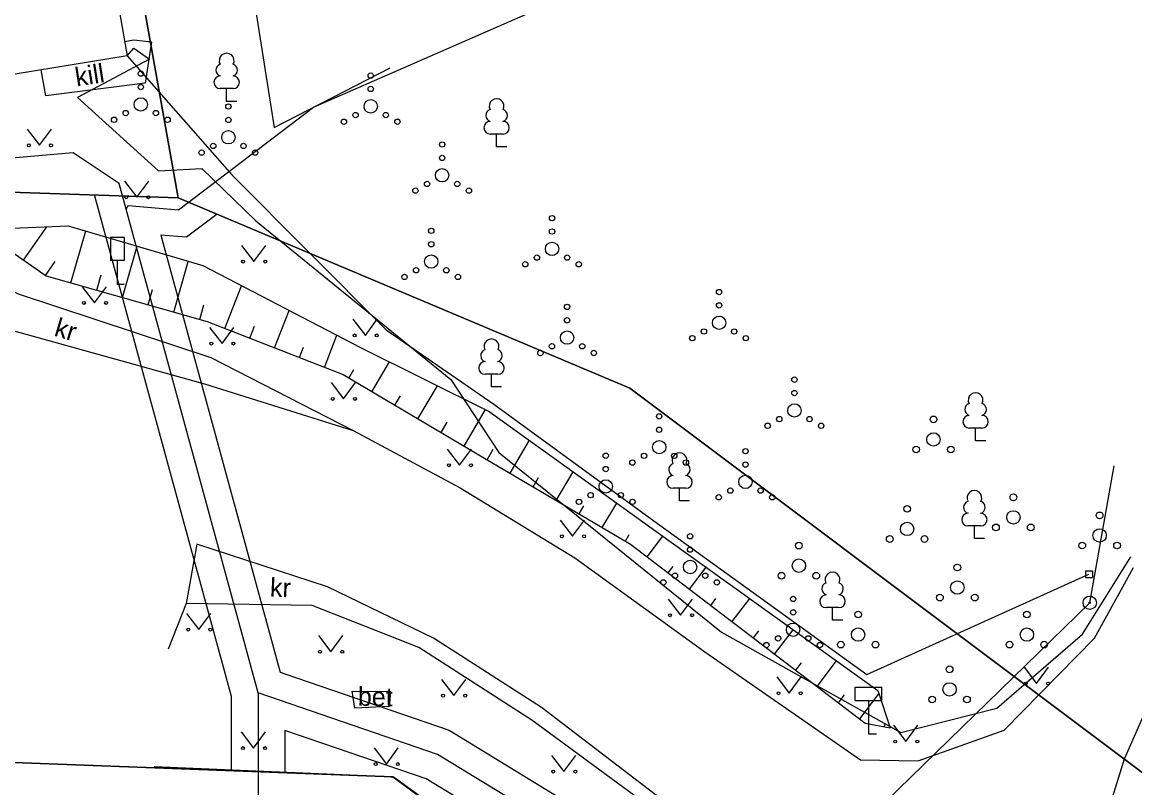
# Model space of a CAD drawing. Extents: x 554947 to 555436, y 6564938 to 6565792.
# Drawn here: x 555228.52 to 555270.11, y 6565583.53 to 6565612.16 of the extents above; entities that cross this region are included whole.
import ezdxf

# ---------------------------------------------------------------- set-up
doc = ezdxf.new("R2010")
doc.units = 0
for name, color, linetype in [('AED', 7, 'Continuous'), ('HALJASTUS', 7, 'Continuous'), ('HOONE', 7, 'Continuous'), ('KASUTUSALA', 7, 'Continuous'), ('LIIKLUS', 7, 'Continuous'), ('MPKAABEL', 7, 'Continuous'), ('MPOHULIIN', 7, 'Continuous'), ('PIIR', 7, 'Continuous'), ('POST', 7, 'Continuous'), ('PR_SIDE', 7, 'Continuous'), ('PUU', 7, 'Continuous'), ('RELJEEF', 7, 'Continuous'), ('TEE', 7, 'Continuous')]:
    doc.layers.add(name, color=color, linetype=linetype)

msp = doc.modelspace()

# ---------------------------------------------------------------- linework, layer by layer
at = {"layer": 'AED'}
for p, q in [((555268.277, 6565591.648), (555268.277, 6565591.398)), ((555268.277, 6565591.648), (555268.527, 6565591.648)), ((555268.527, 6565591.648), (555268.527, 6565591.398)), ((555268.277, 6565591.398), (555268.527, 6565591.398))]:
    msp.add_line(p, q, dxfattribs=at)
for points in [[(555232.436, 6565610.906), (555236.358, 6565606.45), (555242.129, 6565600.656), (555246.155, 6565597.882), (555252.128, 6565593.519), (555260.095, 6565587.775), (555268.402, 6565591.523)], [(555257.388, 6565572.989), (555251.782, 6565577.142), (555242.434, 6565583.901), (555242.233, 6565583.941), (555233.453, 6565584.321)]]:
    msp.add_lwpolyline(points, dxfattribs=at)
at = {"layer": 'HALJASTUS'}
for p, q in [((555228.702, 6565608.164), (555229.166, 6565607.558)), ((555229.166, 6565607.558), (555229.611, 6565608.164)), ((555232.345, 6565606.223), (555232.808, 6565605.616)), ((555232.808, 6565605.616), (555233.254, 6565606.223)), ((555236.713, 6565603.817), (555237.176, 6565603.21)), ((555237.176, 6565603.21), (555237.622, 6565603.817)), ((555230.761, 6565602.272), (555231.225, 6565601.665)), ((555231.225, 6565601.665), (555231.67, 6565602.272)), ((555240.883, 6565601.058), (555241.346, 6565600.451)), ((555241.346, 6565600.451), (555241.792, 6565601.058)), ((555235.524, 6565600.751), (555235.988, 6565600.144)), ((555235.988, 6565600.144), (555236.433, 6565600.751)), ((555240.066, 6565598.683), (555240.53, 6565598.076)), ((555240.53, 6565598.076), (555240.975, 6565598.683)), ((555244.406, 6565596.2), (555244.87, 6565595.593)), ((555244.87, 6565595.593), (555245.315, 6565596.2)), ((555248.633, 6565593.543), (555249.097, 6565592.937)), ((555249.097, 6565592.937), (555249.542, 6565593.543)), ((555252.67, 6565590.593), (555253.134, 6565589.986)), ((555253.134, 6565589.986), (555253.579, 6565590.593)), ((555234.659, 6565590.056), (555235.122, 6565589.45)), ((555235.122, 6565589.45), (555235.568, 6565590.056)), ((555239.59, 6565589.226), (555240.053, 6565588.62)), ((555240.053, 6565588.62), (555240.499, 6565589.226)), ((555265.979, 6565588.04), (555266.442, 6565587.434)), ((555266.442, 6565587.434), (555266.888, 6565588.04)), ((555244.191, 6565587.586), (555244.655, 6565586.979)), ((555244.655, 6565586.979), (555245.1, 6565587.586)), ((555256.732, 6565587.677), (555257.195, 6565587.07)), ((555257.195, 6565587.07), (555257.641, 6565587.677)), ((555236.705, 6565585.623), (555237.169, 6565585.017)), ((555237.169, 6565585.017), (555237.614, 6565585.623)), ((555261.092, 6565585.871), (555261.555, 6565585.264)), ((555261.555, 6565585.264), (555262.001, 6565585.871)), ((555241.67, 6565585.027), (555242.133, 6565584.421)), ((555242.133, 6565584.421), (555242.579, 6565585.027)), ((555248.307, 6565584.746), (555248.77, 6565584.139)), ((555248.77, 6565584.139), (555249.216, 6565584.746))]:
    msp.add_line(p, q, dxfattribs=at)
for points in [[(555237.448, 6565630.434), (555234.711, 6565628.766), (555234.594, 6565621.78), (555237.038, 6565613.917), (555237.935, 6565608.224), (555242.277, 6565610.46)], [(555232.436, 6565610.906), (555232.688, 6565611.189), (555233.276, 6565610.777), (555230.59, 6565609.352), (555233.609, 6565606.609), (555235.228, 6565606.695), (555237.256, 6565604.74), (555244.547, 6565598.797), (555246.343, 6565596.071), (555254.665, 6565589.351), (555261.368, 6565585.597), (555264.956, 6565586.512), (555268.159, 6565589.281), (555269.967, 6565592.17)]]:
    msp.add_lwpolyline(points, dxfattribs=at)
for centre, radius in [((555232.951, 6565610.238), 0.1), ((555241.546, 6565610.166), 0.1), ((555232.951, 6565609.738), 0.1), ((555241.546, 6565609.666), 0.1), ((555232.951, 6565609.088), 0.25), ((555236.225, 6565609.009), 0.1), ((555241.546, 6565609.016), 0.25), ((555231.951, 6565608.513), 0.1), ((555232.386, 6565608.763), 0.1), ((555233.516, 6565608.763), 0.1), ((555233.951, 6565608.513), 0.1), ((555236.225, 6565608.509), 0.1), ((555240.546, 6565608.441), 0.1), ((555240.981, 6565608.691), 0.1), ((555242.111, 6565608.691), 0.1), ((555242.546, 6565608.441), 0.1), ((555236.225, 6565607.859), 0.25), ((555244.218, 6565607.588), 0.1), ((555228.765, 6565607.558), 0.055), ((555229.593, 6565607.558), 0.055), ((555235.225, 6565607.284), 0.1), ((555235.66, 6565607.534), 0.1), ((555236.79, 6565607.534), 0.1), ((555237.225, 6565607.284), 0.1), ((555244.218, 6565607.088), 0.1), ((555244.218, 6565606.438), 0.25), ((555243.653, 6565606.113), 0.1), ((555244.783, 6565606.113), 0.1), ((555232.407, 6565605.616), 0.055), ((555233.236, 6565605.616), 0.055), ((555243.218, 6565605.863), 0.1), ((555245.218, 6565605.863), 0.1), ((555248.326, 6565604.835), 0.1), ((555243.809, 6565604.36), 0.1), ((555248.326, 6565604.335), 0.1), ((555243.809, 6565603.86), 0.1), ((555248.326, 6565603.685), 0.25), ((555236.775, 6565603.21), 0.055), ((555237.604, 6565603.21), 0.055), ((555243.809, 6565603.21), 0.25), ((555247.326, 6565603.11), 0.1), ((555247.761, 6565603.36), 0.1), ((555248.891, 6565603.36), 0.1), ((555249.326, 6565603.11), 0.1), ((555242.809, 6565602.635), 0.1), ((555243.244, 6565602.885), 0.1), ((555244.374, 6565602.885), 0.1), ((555244.809, 6565602.635), 0.1), ((555254.571, 6565602.071), 0.1), ((555230.824, 6565601.665), 0.055), ((555231.652, 6565601.665), 0.055), ((555248.889, 6565601.517), 0.1), ((555254.571, 6565601.571), 0.1), ((555248.889, 6565601.017), 0.1), ((555254.571, 6565600.921), 0.25), ((555248.889, 6565600.367), 0.25), ((555254.006, 6565600.596), 0.1), ((555255.136, 6565600.596), 0.1), ((555235.587, 6565600.144), 0.055), ((555236.415, 6565600.144), 0.055), ((555240.945, 6565600.451), 0.055), ((555241.774, 6565600.451), 0.055), ((555253.571, 6565600.346), 0.1), ((555255.571, 6565600.346), 0.1), ((555247.889, 6565599.792), 0.1), ((555248.324, 6565600.042), 0.1), ((555249.454, 6565600.042), 0.1), ((555249.889, 6565599.792), 0.1), ((555257.388, 6565598.795), 0.1), ((555240.129, 6565598.076), 0.055), ((555240.957, 6565598.076), 0.055), ((555257.388, 6565598.295), 0.1), ((555257.388, 6565597.645), 0.25), ((555252.332, 6565597.421), 0.1), ((555256.823, 6565597.32), 0.1), ((555257.953, 6565597.32), 0.1), ((555252.332, 6565596.921), 0.1), ((555256.388, 6565597.07), 0.1), ((555258.388, 6565597.07), 0.1), ((555252.332, 6565596.271), 0.25), ((555250.334, 6565595.952), 0.1), ((555251.767, 6565595.946), 0.1), ((555252.897, 6565595.946), 0.1), ((555255.558, 6565596.121), 0.1), ((555244.469, 6565595.593), 0.055), ((555245.297, 6565595.593), 0.055), ((555251.332, 6565595.696), 0.1), ((555253.332, 6565595.696), 0.1), ((555255.558, 6565595.621), 0.1), ((555250.334, 6565595.452), 0.1), ((555255.558, 6565594.971), 0.25), ((555250.334, 6565594.802), 0.25), ((555249.769, 6565594.477), 0.1), ((555250.899, 6565594.477), 0.1), ((555254.558, 6565594.396), 0.1), ((555254.993, 6565594.646), 0.1), ((555256.123, 6565594.646), 0.1), ((555256.558, 6565594.396), 0.1), ((555249.334, 6565594.227), 0.1), ((555251.334, 6565594.227), 0.1), ((555248.696, 6565592.937), 0.055), ((555249.525, 6565592.937), 0.055), ((555253.488, 6565592.94), 0.1), ((555253.488, 6565592.44), 0.1), ((555253.488, 6565591.79), 0.25), ((555252.923, 6565591.465), 0.1), ((555254.053, 6565591.465), 0.1), ((555252.488, 6565591.215), 0.1), ((555254.488, 6565591.215), 0.1), ((555257.341, 6565590.594), 0.1), ((555257.341, 6565590.094), 0.1), ((555252.733, 6565589.986), 0.055), ((555253.561, 6565589.986), 0.055), ((555234.721, 6565589.45), 0.055), ((555235.55, 6565589.45), 0.055), ((555257.341, 6565589.444), 0.25), ((555256.341, 6565588.869), 0.1), ((555256.776, 6565589.119), 0.1), ((555257.906, 6565589.119), 0.1), ((555258.341, 6565588.869), 0.1), ((555239.652, 6565588.62), 0.055), ((555240.481, 6565588.62), 0.055), ((555266.041, 6565587.434), 0.055), ((555266.87, 6565587.434), 0.055), ((555244.254, 6565586.979), 0.055), ((555245.082, 6565586.979), 0.055), ((555256.794, 6565587.07), 0.055), ((555257.623, 6565587.07), 0.055), ((555261.154, 6565585.264), 0.055), ((555261.983, 6565585.264), 0.055), ((555236.768, 6565585.017), 0.055), ((555237.597, 6565585.017), 0.055), ((555241.732, 6565584.421), 0.055), ((555242.561, 6565584.421), 0.055), ((555248.369, 6565584.139), 0.055), ((555249.198, 6565584.139), 0.055)]:
    msp.add_circle(centre, radius, dxfattribs=at)
at = {"layer": 'HOONE'}
msp.add_lwpolyline([(555227.207, 6565620.08), (555230.727, 6565620.695), (555232.436, 6565610.906), (555223.594, 6565609.458), (555222.944, 6565613.428)], dxfattribs=at)
at = {"layer": 'KASUTUSALA'}
msp.add_lwpolyline([(555282.937, 6565554.541), (555264.078, 6565568.633), (555259.865, 6565571.933), (555249.017, 6565580.573), (555243.622, 6565583.862), (555238.34, 6565585.678), (555238.34, 6565584.092), (555236.34, 6565584.168), (555236.34, 6565586.946), (555231.217, 6565605.702), (555233.309, 6565605.634), (555234.35, 6565605.6), (555235.803, 6565604.987), (555234.66, 6565604.12), (555233.701, 6565604.199), (555238.103, 6565588.08), (555238.166, 6565587.854), (555238.34, 6565587.793), (555244.478, 6565585.683), (555250.166, 6565582.216), (555261.104, 6565573.503), (555265.293, 6565570.221), (555284.174, 6565556.114)], dxfattribs=at)
at = {"layer": 'LIIKLUS'}
for p, q in [((555231.823, 6565604.106), (555231.823, 6565603.256)), ((555232.323, 6565604.106), (555231.823, 6565604.106)), ((555232.323, 6565604.106), (555232.323, 6565603.256)), ((555232.323, 6565603.256), (555231.823, 6565603.256)), ((555232.073, 6565603.256), (555232.073, 6565602.356)), ((555232.323, 6565602.356), (555232.073, 6565602.356)), ((555259.661, 6565587.299), (555260.661, 6565587.299)), ((555259.661, 6565586.799), (555259.661, 6565587.299)), ((555260.661, 6565586.799), (555260.661, 6565587.299)), ((555259.661, 6565586.799), (555260.661, 6565586.799)), ((555260.161, 6565586.799), (555260.161, 6565585.549)), ((555260.161, 6565585.549), (555260.461, 6565585.549))]:
    msp.add_line(p, q, dxfattribs=at)
at = {"layer": 'MPKAABEL'}
msp.add_lwpolyline([(555232.436, 6565610.906), (555236.358, 6565606.45), (555242.129, 6565600.656), (555246.155, 6565597.882), (555252.128, 6565593.519), (555260.095, 6565587.775), (555268.402, 6565591.523)], dxfattribs=at)
at = {"layer": 'MPOHULIIN'}
for points in [[(555268.428, 6565590.453), (555269.348, 6565595.57)], [(555252.652, 6565575.082), (555268.428, 6565590.453)]]:
    msp.add_lwpolyline(points, dxfattribs=at)
at = {"layer": 'PIIR'}
for points in [[(555193.24, 6565604.68), (555183.94, 6565663.24), (555223.17, 6565668.21), (555234.35, 6565605.6), (555225.47, 6565605.89), (555193.7, 6565602.7)], [(555121.18, 6565602.26), (555138.98, 6565580.6), (555179.42, 6565586.32), (555242.37, 6565583.94), (555302.6, 6565539.71), (555287.77, 6565518.56), (555207.29, 6565506.14), (555200.64, 6565496.23), (555185.97, 6565502.75), (555177.68, 6565506.44), (555171.49, 6565510.85), (555162.05, 6565514.45), (555140.65, 6565513.25), (555139.49, 6565523.98), (555139.26, 6565529.51), (555141.68, 6565537.52), (555139.64, 6565543.1), (555131.01, 6565550.06), (555126.35, 6565558.74), (555119.63, 6565564.84), (555105.26, 6565587.71), (555099.5, 6565594.91), (555116.17, 6565610.5)]]:
    msp.add_lwpolyline(points, close=True, dxfattribs=at)
for points in [[(555374.15, 6565660.24), (555410.9, 6565638.65), (555418.94, 6565635.85), (555435.71, 6565632.72), (555428.83, 6565620.98), (555419.65, 6565609.54), (555361.56, 6565549.57), (555350.68, 6565540.44), (555343.81, 6565536.56), (555330.71, 6565538.85), (555251.24, 6565598.48), (555234.35, 6565605.6), (555223.17, 6565668.21)], [(555144.16, 6565410.6), (555124.27, 6565454.45), (555113.82, 6565475.68), (555076.76, 6565542.38), (555065.78, 6565566.7), (555060.42, 6565583.26), (555057.22, 6565600.73), (555056.61, 6565622.91), (555063.43, 6565647.29), (555114.24, 6565634), (555129.77, 6565611.2), (555130.73, 6565621.32), (555138.66, 6565615.26), (555160.12, 6565598.86), (555193.24, 6565604.68), (555193.7, 6565602.7), (555225.47, 6565605.89), (555234.35, 6565605.6), (555251.24, 6565598.48), (555330.71, 6565538.85), (555343.81, 6565536.56), (555350.68, 6565540.44), (555361.56, 6565549.57), (555393.069, 6565582.099)], [(555393.069, 6565560.972), (555353.12, 6565523.87), (555343.14, 6565512.46), (555302.6, 6565539.71), (555242.37, 6565583.94), (555179.42, 6565586.32), (555138.98, 6565580.6), (555121.18, 6565602.26), (555116.17, 6565610.5), (555109.96, 6565624.83), (555093.56, 6565628.47), (555079.04, 6565618.4), (555074.13, 6565607.82), (555075.34, 6565593.24), (555091.74, 6565551.94), (555171.91, 6565394.64), (555191.35, 6565341.19), (555195.08, 6565294.61), (555195.28, 6565271.63), (555191.64, 6565237.48)]]:
    msp.add_lwpolyline(points, dxfattribs=at)
at = {"layer": 'POST'}
for radius in [0.25, 0.0234]:
    msp.add_circle((555268.428, 6565590.453), radius, dxfattribs=at)
at = {"layer": 'PR_SIDE'}
for points in [[(555232.399, 6565605.169), (555232.478, 6565605.304), (555234.361, 6565605.148), (555239.41, 6565608.98), (555257.145, 6565616.752), (555281.799, 6565659.829), (555291.678, 6565666.126), (555336.528, 6565656.68), (555340.549, 6565660.528)], [(555232.137, 6565606.132), (555230.425, 6565607.283), (555207.996, 6565605.334), (555203.457, 6565604.767), (555201.376, 6565605.797)], [(555309.687, 6565535.684), (555303.916, 6565540.202), (555288.808, 6565550.982), (555283.555, 6565555.328), (555264.686, 6565569.427), (555260.485, 6565572.718), (555249.591, 6565581.395), (555244.05, 6565584.772), (555237.34, 6565587.08), (555232.399, 6565605.169), (555232.137, 6565606.132)], [(555237.34, 6565587.08), (555237.34, 6565565.16), (555226.585, 6565555.364), (555203.636, 6565543.731), (555203.636, 6565538.53), (555204.984, 6565533.828), (555204.645, 6565532.63)]]:
    msp.add_lwpolyline(points, dxfattribs=at)
at = {"layer": 'PUU'}
for p, q in [((555236.401, 6565609.678), (555235.921, 6565609.678)), ((555236.161, 6565609.203), (555236.161, 6565609.678)), ((555236.541, 6565609.203), (555236.161, 6565609.203)), ((555246.494, 6565607.979), (555246.014, 6565607.979)), ((555246.254, 6565607.504), (555246.254, 6565607.979)), ((555246.634, 6565607.504), (555246.254, 6565607.504)), ((555246.301, 6565598.996), (555245.821, 6565598.996)), ((555246.061, 6565598.521), (555246.061, 6565598.996)), ((555246.441, 6565598.521), (555246.061, 6565598.521)), ((555264.402, 6565596.984), (555263.922, 6565596.984)), ((555264.162, 6565596.509), (555264.162, 6565596.984)), ((555264.542, 6565596.509), (555264.162, 6565596.509)), ((555253.33, 6565594.735), (555252.85, 6565594.735)), ((555253.09, 6565594.26), (555253.09, 6565594.735)), ((555253.47, 6565594.26), (555253.09, 6565594.26)), ((555264.357, 6565593.327), (555263.877, 6565593.327)), ((555264.117, 6565592.852), (555264.117, 6565593.327)), ((555264.497, 6565592.852), (555264.117, 6565592.852)), ((555259.054, 6565590.273), (555258.574, 6565590.273)), ((555258.814, 6565589.798), (555258.814, 6565590.273)), ((555259.194, 6565589.798), (555258.814, 6565589.798))]:
    msp.add_line(p, q, dxfattribs=at)
for centre, radius in [((555262.588, 6565597.311), 0.125), ((555262.588, 6565596.561), 0.25), ((555261.938, 6565596.186), 0.125), ((555263.238, 6565596.186), 0.125), ((555265.574, 6565594.395), 0.125), ((555261.601, 6565593.962), 0.125), ((555265.574, 6565593.645), 0.25), ((555268.8, 6565593.721), 0.125), ((555261.601, 6565593.212), 0.25), ((555264.924, 6565593.27), 0.125), ((555266.224, 6565593.27), 0.125), ((555268.8, 6565592.971), 0.25), ((555257.556, 6565592.589), 0.125), ((555260.951, 6565592.837), 0.125), ((555262.251, 6565592.837), 0.125), ((555268.15, 6565592.596), 0.125), ((555269.45, 6565592.596), 0.125), ((555257.556, 6565591.839), 0.25), ((555263.479, 6565591.77), 0.125), ((555256.906, 6565591.464), 0.125), ((555258.206, 6565591.464), 0.125), ((555263.479, 6565591.02), 0.25), ((555262.829, 6565590.645), 0.125), ((555264.129, 6565590.645), 0.125), ((555259.771, 6565590.011), 0.125), ((555266.079, 6565590.011), 0.125), ((555259.771, 6565589.261), 0.25), ((555266.079, 6565589.261), 0.25), ((555259.121, 6565588.886), 0.125), ((555260.421, 6565588.886), 0.125), ((555265.429, 6565588.886), 0.125), ((555266.729, 6565588.886), 0.125), ((555263.19, 6565587.963), 0.125), ((555263.19, 6565587.213), 0.25), ((555262.54, 6565586.838), 0.125), ((555263.84, 6565586.838), 0.125)]:
    msp.add_circle(centre, radius, dxfattribs=at)
for centre, radius, start, end in [((555236.161, 6565610.723), 0.277, 332.5799, 207.4201), ((555235.991, 6565610.375), 0.233, 109.0217, 253.1415), ((555236.331, 6565610.375), 0.233, 286.8508, 70.9859), ((555235.924, 6565609.915), 0.238, 90.0016, 269.3953), ((555236.398, 6565609.915), 0.238, 270.6047, 89.9984), ((555246.254, 6565609.024), 0.277, 332.5799, 207.4201), ((555246.084, 6565608.676), 0.233, 109.0217, 253.1415), ((555246.424, 6565608.676), 0.233, 286.8508, 70.9859), ((555246.016, 6565608.216), 0.238, 90.0016, 269.3953), ((555246.491, 6565608.216), 0.238, 270.6047, 89.9984), ((555246.061, 6565600.041), 0.277, 332.5799, 207.4201), ((555245.891, 6565599.694), 0.233, 109.0217, 253.1415), ((555246.231, 6565599.694), 0.233, 286.8508, 70.9859), ((555245.824, 6565599.234), 0.238, 90.0016, 269.3953), ((555246.299, 6565599.234), 0.238, 270.6047, 89.9984), ((555264.162, 6565598.029), 0.277, 332.5799, 207.4201), ((555263.992, 6565597.681), 0.233, 109.0217, 253.1415), ((555264.332, 6565597.681), 0.233, 286.8508, 70.9859), ((555263.925, 6565597.221), 0.238, 90.0016, 269.3953), ((555264.399, 6565597.221), 0.238, 270.6047, 89.9984), ((555253.09, 6565595.781), 0.277, 332.5799, 207.4201), ((555252.92, 6565595.433), 0.233, 109.0217, 253.1415), ((555253.26, 6565595.433), 0.233, 286.8508, 70.9859), ((555252.853, 6565594.973), 0.238, 90.0016, 269.3953), ((555253.328, 6565594.973), 0.238, 270.6047, 89.9984), ((555264.117, 6565594.372), 0.277, 332.5799, 207.4201), ((555263.947, 6565594.024), 0.233, 109.0217, 253.1415), ((555264.287, 6565594.024), 0.233, 286.8508, 70.9859), ((555263.88, 6565593.564), 0.238, 90.0016, 269.3953), ((555264.355, 6565593.564), 0.238, 270.6047, 89.9984), ((555258.814, 6565591.318), 0.277, 332.5799, 207.4201), ((555258.644, 6565590.971), 0.233, 109.0217, 253.1415), ((555258.984, 6565590.971), 0.233, 286.8508, 70.9859), ((555258.576, 6565590.51), 0.238, 90.0016, 269.3953), ((555259.051, 6565590.51), 0.238, 270.6047, 89.9984)]:
    msp.add_arc(centre, radius, start, end, dxfattribs=at)
at = {"layer": 'RELJEEF'}
for p, q in [((555228.564, 6565603.267), (555229.436, 6565604.515)), ((555230.341, 6565602.411), (555230.892, 6565604.355)), ((555232.266, 6565601.867), (555232.809, 6565603.787)), ((555229.384, 6565602.695), (555229.75, 6565603.218)), ((555234.19, 6565601.322), (555234.727, 6565603.219)), ((555231.303, 6565602.139), (555231.468, 6565602.719)), ((555236.092, 6565600.712), (555236.716, 6565602.307)), ((555233.228, 6565601.594), (555233.39, 6565602.167)), ((555235.152, 6565601.049), (555235.305, 6565601.59)), ((555237.955, 6565599.984), (555238.501, 6565601.381)), ((555237.024, 6565600.348), (555237.199, 6565600.797)), ((555239.818, 6565599.256), (555240.286, 6565600.454)), ((555238.887, 6565599.62), (555239.039, 6565600.009)), ((555241.592, 6565598.346), (555242.251, 6565599.46)), ((555240.732, 6565598.855), (555240.918, 6565599.17)), ((555243.314, 6565597.328), (555244.047, 6565598.568)), ((555242.453, 6565597.837), (555242.662, 6565598.19)), ((555245.035, 6565596.31), (555245.843, 6565597.676)), ((555244.175, 6565596.819), (555244.406, 6565597.21)), ((555246.758, 6565595.294), (555247.484, 6565596.527)), ((555245.896, 6565595.801), (555246.128, 6565596.195)), ((555248.482, 6565594.28), (555249.114, 6565595.354)), ((555247.62, 6565594.787), (555247.824, 6565595.133)), ((555249.344, 6565593.773), (555249.519, 6565594.071)), ((555250.206, 6565593.266), (555250.744, 6565594.182)), ((555251.067, 6565592.758), (555251.215, 6565593.009)), ((555251.877, 6565592.174), (555252.465, 6565592.945)), ((555252.672, 6565591.567), (555252.854, 6565591.805)), ((555253.467, 6565590.961), (555254.091, 6565591.778)), ((555254.262, 6565590.354), (555254.455, 6565590.606)), ((555255.057, 6565589.748), (555255.716, 6565590.611)), ((555255.853, 6565589.141), (555256.055, 6565589.407)), ((555256.648, 6565588.535), (555257.341, 6565589.444)), ((555257.443, 6565587.928), (555257.656, 6565588.208)), ((555258.238, 6565587.322), (555258.966, 6565588.277)), ((555259.033, 6565586.715), (555259.257, 6565587.009)), ((555259.828, 6565586.109), (555260.546, 6565587.049)), ((555260.761, 6565585.812), (555260.782, 6565585.923))]:
    msp.add_line(p, q, dxfattribs=at)
for points in [[(555226.924, 6565604.412), (555230.239, 6565604.548), (555235.266, 6565603.059), (555241.163, 6565600), (555245.981, 6565597.608), (555251.809, 6565593.416), (555260.505, 6565587.172), (555260.967, 6565585.773)], [(555226.924, 6565604.412), (555229.414, 6565602.674), (555235.432, 6565600.97), (555240.514, 6565598.984), (555245.865, 6565595.82), (555251.258, 6565592.646), (555260.036, 6565585.95), (555260.967, 6565585.773)]]:
    msp.add_lwpolyline(points, dxfattribs=at)
at = {"layer": 'TEE'}
for points in [[(555232.343, 6565611.444), (555232.688, 6565611.504), (555233.346, 6565611.432), (555233.113, 6565609.886)], [(555233.113, 6565609.886), (555229.405, 6565609.408), (555229.229, 6565610.381)], [(555222.826, 6565609.775), (555223.534, 6565606.972), (555224.328, 6565605.219), (555225.968, 6565603.202), (555228.36, 6565602.005), (555235.567, 6565599.627), (555240.887, 6565596.891)], [(555188.66, 6565597.281), (555201.537, 6565599.665), (555208.847, 6565600.64), (555216.336, 6565601.179), (555217.666, 6565602.458), (555221.722, 6565602.33), (555228.473, 6565600.549), (555235.333, 6565598.633), (555240.887, 6565596.891), (555244.887, 6565594.749), (555249.174, 6565592.129), (555254.043, 6565588.613), (555259.862, 6565584.582), (555262.011, 6565584.54), (555265.231, 6565585.691), (555268.603, 6565589.126), (555270.071, 6565591.77)], [(555309.906, 6565538.03), (555305.168, 6565541.808), (555305.066, 6565542.334), (555294.766, 6565550.531), (555276.823, 6565564.276), (555265.732, 6565572.927), (555259.684, 6565577.587), (555254.787, 6565581.289), (555247.931, 6565586.532), (555243.893, 6565589.125), (555239.934, 6565591.048), (555235.042, 6565592.642), (555234.652, 6565590.428), (555233.978, 6565588.723)], [(555254.087, 6565579.537), (555253.958, 6565580.81), (555252.655, 6565582.326), (555247.572, 6565586.061), (555243.345, 6565588.774), (555239.362, 6565590.351), (555234.652, 6565590.428)], [(555272.683, 6565590.134), (555271.484, 6565588.076), (555270.516, 6565586.416), (555269.723, 6565584.609), (555268.981, 6565582.24), (555268.55, 6565578.954), (555269.504, 6565576.952), (555281.044, 6565568.103), (555297.768, 6565555.508), (555316.66, 6565541.129), (555323.074, 6565536.252), (555328.036, 6565533.009), (555332.837, 6565530.879), (555337.611, 6565529.695), (555343.363, 6565529.946), (555348.456, 6565531.532), (555353.801, 6565534.677), (555358.561, 6565538.499)], [(555240.854, 6565587.15), (555242.289, 6565587.129), (555242.241, 6565586.577), (555240.956, 6565586.51), (555240.854, 6565587.15)]]:
    msp.add_lwpolyline(points, dxfattribs=at)

# ---------------------------------------------------------------- texts
for s, rotation, p in [('kill', 9.0562, (555230.552, 6565609.756)), ('kr', 343.3686, (555229.676, 6565600.446)), ('kr', 357.4887, (555237.769, 6565590.687)), ('bet', 359.1358, (555241.063, 6565586.6))]:
    msp.add_text(s, height=0.7, rotation=rotation, dxfattribs=at).set_placement(p)

doc.saveas('drawing.dxf')
